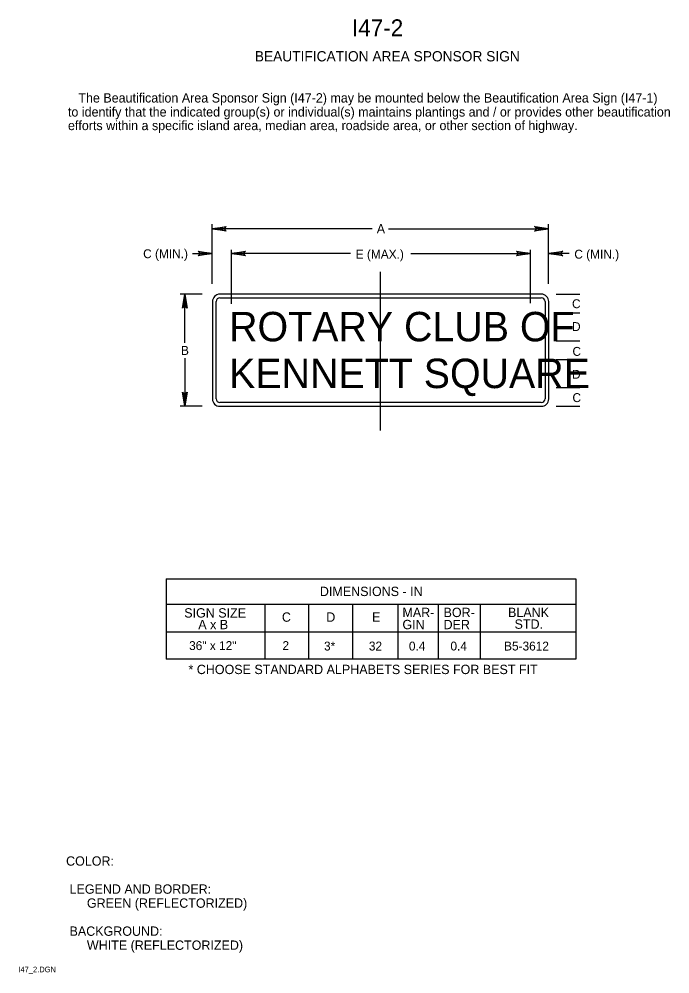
# Model space of a CAD drawing. Extents: x 0.013 to 0.187, y 0.004 to 0.259.
import ezdxf

# ---------------------------------------------------------------- set-up
doc = ezdxf.new("R2010")
doc.units = 0
for name, color, linetype in [('1', 7, 'Continuous'), ('2', 7, 'Continuous'), ('3', 7, 'Continuous')]:
    doc.layers.add(name, color=color, linetype=linetype)

# ---------------------------------------------------------------- blocks, each defined once
blk = doc.blocks.new('RARROW')
at = {"layer": '3'}
for p, q in [((-2.156, 0.285), (-2.2665, 0.384625)), ((-2.2665, 0.384625), (0, 0)), ((0, 0), (-2.2665, -0.379125)), ((-2.156, 0.285), (-2.075625, 0.12075)), ((0, 0), (-2.156, 0.285)), ((-2.14975, -0.2705), (0, 0)), ((-2.075625, 0.12075), (0, 0)), ((0, 0), (-2.074, -0.108)), ((-2.2665, -0.379125), (-2.14975, -0.2705)), ((-2.074, -0.108), (-2.14975, -0.2705))]:
    blk.add_line(p, q, dxfattribs=at)

msp = doc.modelspace()

# ---------------------------------------------------------------- linework, layer by layer
at = {"layer": '3'}
for p, q in [((0.06425, 0.1885), (0.06425, 0.2045)), ((0.15425, 0.1885), (0.15425, 0.2045)), ((0.107, 0.20325), (0.06425, 0.20325)), ((0.11138, 0.20325), (0.15425, 0.20325)), ((0.06938, 0.18313), (0.06938, 0.19762)), ((0.14938, 0.18338), (0.14938, 0.19762)), ((0.059, 0.19662), (0.06425, 0.19662)), ((0.07337, 0.19662), (0.06938, 0.19662)), ((0.10125, 0.19662), (0.06938, 0.19662)), ((0.11738, 0.19662), (0.14938, 0.19662)), ((0.15975, 0.19662), (0.15425, 0.19662)), ((0.10925, 0.14925), (0.10925, 0.19175)), ((0.0615, 0.18575), (0.05563, 0.18575)), ((0.05688, 0.17275), (0.05688, 0.18575)), ((0.15229, 0.18575), (0.06629, 0.18575)), ((0.06629, 0.18475), (0.15229, 0.18475)), ((0.15625, 0.18575), (0.16262, 0.18575)), ((0.06429, 0.18375), (0.06429, 0.15775)), ((0.06529, 0.15775), (0.06529, 0.18375)), ((0.15329, 0.18375), (0.15329, 0.15775)), ((0.15429, 0.15775), (0.15429, 0.18375)), ((0.15625, 0.18075), (0.16262, 0.18075)), ((0.15625, 0.17325), (0.16262, 0.17325)), ((0.05688, 0.16862), (0.05688, 0.15575)), ((0.15625, 0.16825), (0.16262, 0.16825)), ((0.15625, 0.16075), (0.16262, 0.16075)), ((0.15229, 0.15675), (0.06629, 0.15675)), ((0.0615, 0.15575), (0.05563, 0.15575)), ((0.06629, 0.15575), (0.15229, 0.15575)), ((0.15625, 0.15575), (0.16262, 0.15575)), ((0.05188, 0.10963), (0.1615, 0.10963)), ((0.05188, 0.10963), (0.05188, 0.08812)), ((0.16154, 0.10962), (0.16154, 0.08812)), ((0.1615, 0.10275), (0.05188, 0.10275)), ((0.07829, 0.10275), (0.07829, 0.08812)), ((0.09, 0.10275), (0.09, 0.08812)), ((0.10175, 0.10275), (0.10175, 0.08812)), ((0.11392, 0.10275), (0.11392, 0.08812)), ((0.12467, 0.10275), (0.12467, 0.08812)), ((0.13596, 0.10275), (0.13596, 0.08812)), ((0.1615, 0.09538), (0.05188, 0.09538)), ((0.1615, 0.08812), (0.05188, 0.08812))]:
    msp.add_line(p, q, dxfattribs=at)
for centre, radius, start, end in [((0.06629, 0.18375), 0.002, 90, 180), ((0.06629, 0.18375), 0.001, 90, 180), ((0.15229, 0.18375), 0.002, 0, 90), ((0.15229, 0.18375), 0.001, 0, 90), ((0.06629, 0.15775), 0.002, 180, 270), ((0.06629, 0.15775), 0.001, 180, 270), ((0.15229, 0.15775), 0.002, 270, 0), ((0.15229, 0.15775), 0.001, 270, 0)]:
    msp.add_arc(centre, radius, start, end, dxfattribs=at)

# ---------------------------------------------------------------- block references
at = {"layer": '3', "xscale": 0.0016545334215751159, "yscale": 0.0016366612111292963}
for p, rotation in [((0.06425, 0.20325), 180), ((0.06938, 0.19662), 180), ((0.15425, 0.19662), 180), ((0.05688, 0.18575), 90), ((0.05688, 0.15575), -90)]:
    msp.add_blockref('RARROW', p, dxfattribs=dict(at, rotation=rotation))
for p in [(0.15425, 0.20325), (0.06425, 0.19662), (0.14938, 0.19662)]:
    msp.add_blockref('RARROW', p, dxfattribs=at)

# ---------------------------------------------------------------- texts
at = {"layer": '1'}
for s, height, p in [('I47-2', 0.0045, (0.10163, 0.25475)), ('BEAUTIFICATION AREA SPONSOR SIGN', 0.0027503, (0.07562, 0.248)), ('COLOR:', 0.0025, (0.02513, 0.03288)), (' LEGEND AND BORDER:', 0.0024998, (0.02513, 0.02538)), ('      GREEN (REFLECTORIZED)', 0.0024998, (0.02513, 0.02163)), (' BACKGROUND:', 0.0024998, (0.02513, 0.01413)), ('      WHITE (REFLECTORIZED)', 0.0024998, (0.02513, 0.01038)), ('I47_2.DGN', 0.0015, (0.01238, 0.00438))]:
    msp.add_text(s, height=height, dxfattribs=at).set_placement(p)
at = {"layer": '2'}
for s, height, p in [('   The Beautification Area Sponsor Sign (I47-2) may be mounted below the Beautification Area Sign (I47-1)', 0.00249975, (0.02563, 0.237)), ('to identify that the indicated group(s) or individual(s) maintains plantings and / or provides other beautification', 0.00249975, (0.02563, 0.23325)), ('efforts within a specific island area, median area, roadside area, or other section of highway.', 0.0024998, (0.02563, 0.22962))]:
    msp.add_text(s, height=height, dxfattribs=at).set_placement(p)
at = {"layer": '3'}
for s, height, p in [('A', 0.0025, (0.10825, 0.202)), ('C (MIN.)', 0.002375, (0.04575, 0.19537)), ('E (MAX.)', 0.002375, (0.10263, 0.19525)), ('C (MIN.)', 0.002375, (0.16112, 0.19525)), ('C', 0.00238, (0.1605, 0.182)), ('ROTARY CLUB OF', 0.0078742, (0.06875, 0.17313)), ('D', 0.00238, (0.1605, 0.17588)), ('B', 0.00238, (0.05588, 0.1695)), ('C', 0.00238, (0.16062, 0.16925)), ('KENNETT SQUARE', 0.007875, (0.06875, 0.16062)), ('D', 0.00238, (0.1605, 0.16312)), ('C', 0.00238, (0.16062, 0.15688)), ('DIMENSIONS - IN', 0.0024998, (0.09305, 0.105)), ('SIGN SIZE', 0.0025, (0.05675, 0.09925)), ('C', 0.0025, (0.08288, 0.09813)), ('D', 0.0025, (0.09475, 0.09813)), ('E', 0.0025, (0.10699, 0.09813)), ('MAR-', 0.0025, (0.11513, 0.09938)), ('BOR-', 0.0025, (0.12613, 0.09938)), ('BLANK', 0.0025, (0.14338, 0.09938)), ('A x B', 0.0025, (0.0605, 0.09613)), ('GIN', 0.0025, (0.11513, 0.09613)), ('DER', 0.0025, (0.12613, 0.09613)), ('STD.', 0.0025, (0.14513, 0.09625)), ('36" x 12"', 0.002375, (0.05805, 0.09056)), ('2', 0.00238, (0.08302, 0.09056)), ('3*', 0.002375, (0.09414, 0.09044)), ('32', 0.002375, (0.10614, 0.09044)), ('0.4', 0.002375, (0.11686, 0.09044)), ('0.4', 0.002375, (0.12798, 0.09044)), ('B5-3612', 0.002375, (0.14232, 0.09044)), ('* CHOOSE STANDARD ALPHABETS SERIES FOR BEST FIT', 0.0024998, (0.05788, 0.08413))]:
    msp.add_text(s, height=height, dxfattribs=at).set_placement(p)

doc.saveas('drawing.dxf')
